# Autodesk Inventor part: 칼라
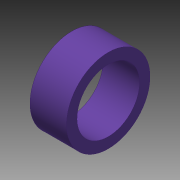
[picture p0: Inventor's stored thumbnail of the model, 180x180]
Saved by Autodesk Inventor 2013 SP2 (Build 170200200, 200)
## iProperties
Created: 2020-04
Part Number: 칼라
Material: 강철, 연강
Document SubType Name: Modeling
Designer: mduedu
Density: 7.86 g/cm^3
Mass: 4.83981 g
Surface Area: 7.91681 cm^2
Volume: 0.615752 cm^3
Author: mduedu
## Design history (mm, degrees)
sketch "스케치1"
  geometry: C1 r 8 at (0, 0); C2 r 6 at (0, 0); 1 further point
  constraints: 2 centre point, 2 coincident
  dimensions: "d0" = 16 diameter of C1; "d1" = 12 diameter of C2
extrude "돌출1" new body sketch "스케치1" distance "d2" = 7; taper "d3" = 0 deg
node "솔리드1"
